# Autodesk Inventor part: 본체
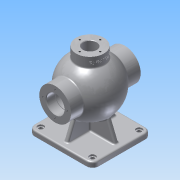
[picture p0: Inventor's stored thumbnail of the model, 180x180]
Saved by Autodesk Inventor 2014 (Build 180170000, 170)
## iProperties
Created: 2017-01
Part Number: 본체
Material: Aluminum 6061
Document SubType Name: Modeling
Designer: ksu
Density: 2.71 g/cm^3
Appearance: Aluminum - Flat
Author: ksu
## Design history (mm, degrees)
sketch "Sketch1"
  geometry: L1 (0, 53)-(0, -53); A1 r 53 centre (0, 0) between (0, -53) and (0, 53); 1 further point
  constraints: 2 end point, 2 point on circle, 1 centre point, 1 coincident
  dimensions: "d0" = 106 diameter of A1
revolve "Revolution1" sketch "Sketch1" stored, may be unused: angle "d1" = 90 deg
workplane "Work Plane1"
sketch "Sketch2"
  geometry: L1 (-62.5, 57.5)-(62.5, 57.5); L2 (62.5, 57.5)-(62.5, -57.5); L3 (62.5, -57.5)-(-62.5, -57.5); L4 (-62.5, -57.5)-(-62.5, 57.5); L5 (-62.5, 57.5)-(62.5, -57.5); L6 (62.5, 57.5)-(-62.5, -57.5); 1 further point
  constraints: 12 end point, 2 midpoint, 2 parallel, 1 horizontal, 1 perpendicular
  dimensions: "d3" = 125 distance of L2.end L3.end; "d4" = 115 distance of L1.end L2.end
extrude "Extrusion1" join sketch "Sketch2" distance "d5" = 10; taper "d6" = 0 deg
sketch "Sketch4"
  geometry: C1 r 53 at (0, 0) reference; C2 r 31 at (0, 0); 1 further point
  constraints: 1 centre point, 1 coincident
  dimensions: "d9" = 62 diameter of C2
extrude "Extrusion2" join sketch "Sketch4" stored distance "d10" = 136; taper "d11" = 0 deg
sketch "Sketch5"
  geometry: L1 (-31, 42.988)-(31, 42.988) reference; L2 (31, -42.988)-(-31, -42.988) reference; L3 (-85, -57.5)-(-85, 57.5) reference; L4 (-85, -57.5)-(-75, -57.5) reference; L5 (-75, 57.5)-(-75, -57.5) reference; L6 (-85, 57.5)-(-75, 57.5) reference; L7 (-75, 47.5)-(-29.078, 28.946); L8 (-29.078, 28.946)-(-29.078, 0); L9 (-75, 47.5)-(-75, 0); L10 (-75, -47.5)-(-29.078, -28.946); L11 (-29.078, -28.946)-(-29.078, 0); L12 (-75, -47.5)-(-75, 47.5); 3 further points
  constraints: 12 end point, 1 midpoint, 1 point on line
extrude "Extrusion3" join sketch "Sketch5" stored distance "d14" = 8; taper "d15" = 0 deg
workplane "Work Plane2"
sketch "Sketch7"
  geometry: C1 r 27 at (0, 0); A1 r 53 centre (0, 0) between (-31, 42.988) and (31, 42.988) reference; 1 further point
  constraints: 1 centre point, 1 coincident
  dimensions: "d21" = 54 diameter of C1
extrude "Extrusion5" join sketch "Sketch7" distance "d22" = 20; taper "d23" = 0 deg
sketch "Sketch8"
  geometry: C1 r 27 at (0, 0) reference; C2 r 13 at (0, 0)
  constraints: 1 centre point, 1 coincident
  dimensions: "d24" = 26 diameter of C2
extrude "Extrusion6" cut sketch "Sketch8" distance "d25" = 50; taper "d26" = 0 deg
sketch "Sketch9"
  geometry: C1 r 31 at (0, 0) reference; C2 r 17.5 at (0, 0)
  constraints: 1 centre point, 1 coincident
  dimensions: "d27" = 35 diameter of C2
extrude "Extrusion7" cut sketch "Sketch9" stored distance "d28" = 50; taper "d29" = 0 deg
sketch "Sketch10"
  geometry: L1 (43, 0)-(-43, 0); A1 r 53 centre (0, 0) between (-40.891, -33.719) and (-40.891, 33.719) reference; A2 r 43 centre (0, 0) between (-43, 0) and (43, 0); 1 further point
  constraints: 2 end point, 2 point on circle, 1 centre point, 1 coincident, 1 horizontal
  dimensions: "d30" = 86 diameter of A2
revolve "Revolution2" sketch "Sketch10" stored, may be unused: angle "d31" = 90 deg
workplane "Work Plane3"
sketch "Sketch11"
  geometry: C1 r 18.5 at (0, 0); C2 r 17.5 at (0, 0) reference; C3 r 17.5 at (0, 0)
  constraints: 2 centre point, 1 coincident, 1 concentric
extrude "Extrusion8" cut sketch "Sketch11" distance "d37" = 1.75; taper "d38" = 0 deg
workplane "Work Plane5"
workplane "Work Plane6"
sketch "Sketch14"
  geometry: L1 (65, -27)-(65, 27) reference; L2 (45.607, 27)-(45.607, -27) reference; L3 (96.296, 31.332)-(96.296, -31.332); L4 (96.296, -31.332)-(13.704, -31.332); L5 (13.704, -31.332)-(13.704, 31.332); L6 (13.704, 31.332)-(96.296, 31.332); 1 further point
  constraints: 2 other
emboss "Emboss2" sketch "Sketch14" dims "d47" = 0.5, "d48" = 0
sketch "Sketch16"
  geometry: 4 further points
hole "Hole2" sketch "Sketch16" diameter "d59" = 3.459; stored, may be unused: countersink angle "d63" = 90 deg, drill point angle "d65" = 118 deg; dims "d60" = 16, "d61" = 4, "d62" = 2, "d64" = 19
sketch "Sketch17"
  geometry: 5 further points
hole "Hole3" sketch "Sketch17" at (-50.5, 45.5), (-50.5, -45.5), (50.5, -45.5), (50.5, 45.5) diameter "d68" = 8; stored, may be unused: countersink angle "d72" = 90 deg, drill point angle "d74" = 0 deg; dims "d69" = 16, "d70" = 12, "d71" = 3, "d73" = 19
fillet "Fillet1" dims "d75" = 12
chamfer "Chamfer1" distance "d76" = 1; stored, may be unused: second distance "d77" = 2, angle "d78" = 45 deg
chamfer "Chamfer2" distance "d79" = 1; stored, may be unused: second distance "d80" = 2, angle "d81" = 45 deg
chamfer "Chamfer3" distance "d82" = 1; stored, may be unused: second distance "d83" = 2, angle "d84" = 45 deg
fillet "Fillet2" dims "d85" = 3
fillet "Fillet3" dims "d86" = 3
fillet "Fillet4" dims "d87" = 3
sketch "Sketch18"
  geometry: 4 further points
hole "Hole4" sketch "Sketch18" at (0, 20), (0, -20), (-20, 0), (20, 0) diameter "d91" = 3.459; stored, may be unused: countersink angle "d95" = 90 deg, drill point angle "d97" = 118 deg; dims "d92" = 9, "d93" = 4, "d94" = 2, "d96" = 11
sketch "Sketch19"
  geometry: L1 (-50.5, -85)-(50.5, -85) reference; L2 (-62.5, -85)-(-62.5, -78) reference; L3 (-56.5, -75)-(-44.5, -75) reference; L4 (-52.5, -75)-(-35.399, -32.673); L5 (-52.5, -75)-(0, -75); L6 (52.5, -75)-(35.399, -32.673); L7 (52.5, -75)-(0, -75); A1 r 53 centre (0, 0) between (-28.393, 44.753) and (28.393, 44.753) reference; A2 r 48.172 centre (0, 0) between (-35.399, -32.673) and (35.399, -32.673); 3 further points
  constraints: 8 end point, 3 point on line, 2 point on circle, 1 centre point
extrude "Extrusion9" join sketch "Sketch19" stored distance "d100" = 8; taper "d101" = 0 deg
fillet "Fillet10" dims "d105" = 3
fillet "Fillet11" dims "d106" = 3
fillet "Fillet12" dims "d107" = 3
sketch "Sketch21"
  geometry: 4 further points
hole "Hole6" sketch "Sketch21" at (0, 22.5), (-22.5, 0), (22.5, 0), (0, -22.5) diameter "d118" = 3.459; stored, may be unused: countersink angle "d122" = 90 deg, drill point angle "d124" = 118 deg; dims "d119" = 12, "d120" = 4, "d121" = 2, "d123" = 15
sketch "Sketch22"
  geometry: 4 further points
hole "Hole7" sketch "Sketch22" at (0, 24), (0, -24), (-24, 0), (24, 0) diameter "d126" = 3.459; stored, may be unused: countersink angle "d130" = 90 deg, drill point angle "d132" = 118 deg; dims "d127" = 16, "d128" = 4, "d129" = 2, "d131" = 19
body "Solid1"
node "Projected Loop1"
node "Projected Loop2"
node "Projected Loop5"
other parameters: "d2" = -85, "d32" = -16, "d40" = 27, "d45" = 27
